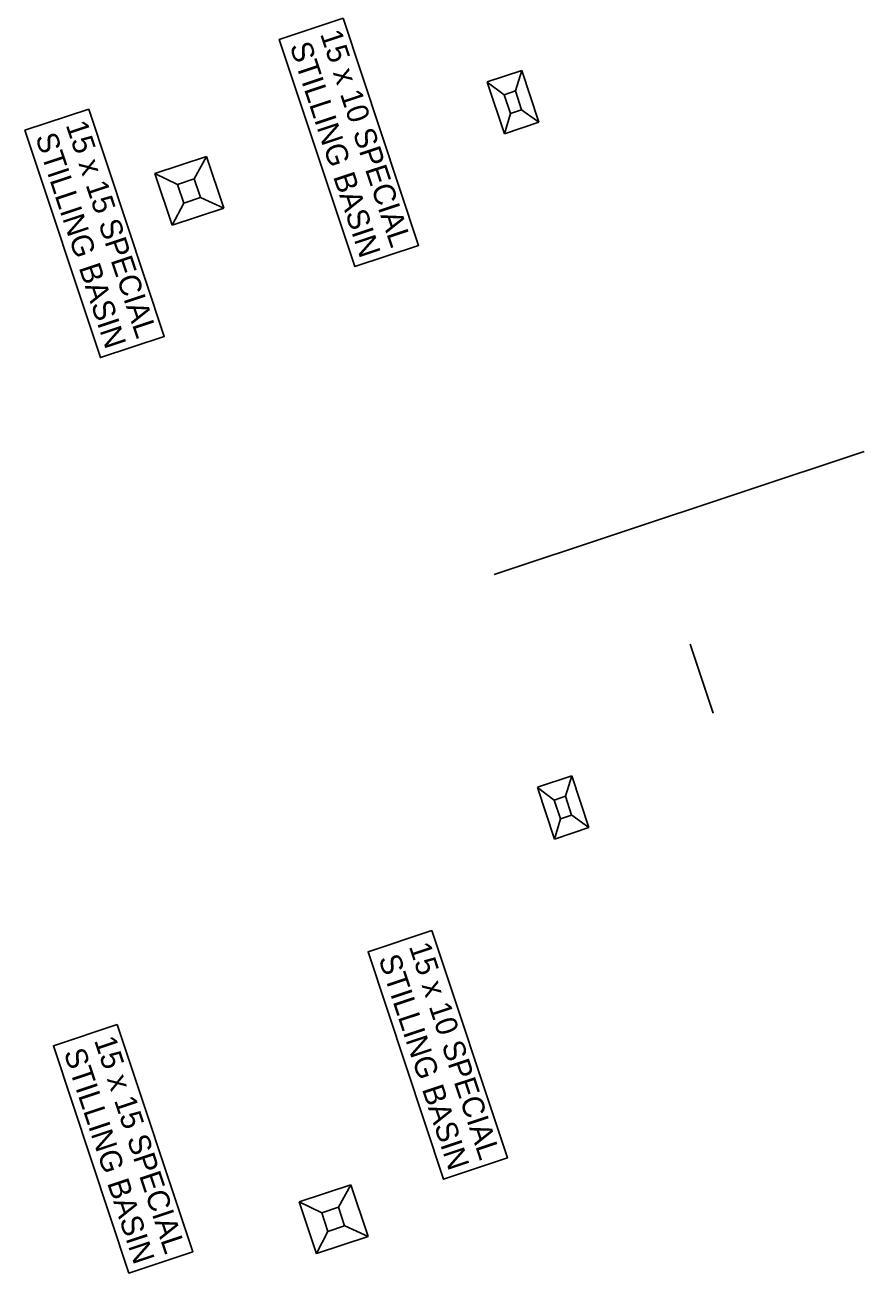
# Model space of a CAD drawing. Extents: x 400935 to 481562, y 415700 to 505362.
# Drawn here: x 401542.1 to 401773.5, y 419185.6 to 419529.4 of the extents above; entities that cross this region are included whole.
import ezdxf

# ---------------------------------------------------------------- set-up
doc = ezdxf.new("R2010")
doc.units = 0
for name, color, linetype in [('Slope Drain Final', 7, 'Continuous'), ('Slope Drain Inlet Final CELL', 7, 'Continuous'), ('Special Stilling Basin 15 x 10 Both CELL', 7, 'Continuous'), ('Special Stilling Basin 15 x 10 Final CELL', 7, 'Continuous'), ('Special Stilling Basin 15 x 10 Note Both CELL', 7, 'Continuous'), ('Special Stilling Basin 15 x 10 Note Final CELL', 7, 'Continuous'), ('Special Stilling Basin 15 x 15 Both CELL', 7, 'Continuous'), ('Special Stilling Basin 15 x 15 Final CELL', 7, 'Continuous'), ('Special Stilling Basin 15 x 15 Note Both CELL', 7, 'Continuous'), ('Special Stilling Basin 15 x 15 Note Final CELL', 7, 'Continuous')]:
    doc.layers.add(name, color=color, linetype=linetype)

msp = doc.modelspace()

# ---------------------------------------------------------------- linework, layer by layer
at = {"layer": 'Slope Drain Final'}
msp.add_line((401773.48, 419411.91), (401671.5, 419378.01), dxfattribs=at)
msp.add_line((401773.48, 419411.91), (401671.5, 419378.01), dxfattribs=at)
msp.add_line((401773.48, 419411.91), (401671.5, 419378.01), dxfattribs=at)
msp.add_line((401773.48, 419411.91), (401671.5, 419378.01), dxfattribs=at)
msp.add_line((401773.48, 419411.91), (401671.5, 419378.01), dxfattribs=at)
msp.add_line((401773.48, 419411.91), (401671.5, 419378.01), dxfattribs=at)
at = {"layer": 'Slope Drain Inlet Final CELL'}
msp.add_line((401725.56, 419358.83), (401731.87, 419339.85), dxfattribs=at)
msp.add_line((401725.56, 419358.83), (401731.87, 419339.85), dxfattribs=at)
msp.add_line((401725.56, 419358.83), (401731.87, 419339.85), dxfattribs=at)
msp.add_line((401725.56, 419358.83), (401731.87, 419339.85), dxfattribs=at)
msp.add_line((401725.56, 419358.83), (401731.87, 419339.85), dxfattribs=at)
msp.add_line((401725.56, 419358.83), (401731.87, 419339.85), dxfattribs=at)
at = {"layer": 'Special Stilling Basin 15 x 10 Both CELL'}
for p, q in [((401669.62, 419513.72), (401679.11, 419516.86)), ((401669.62, 419513.72), (401679.11, 419516.86)), ((401669.62, 419513.72), (401679.11, 419516.86)), ((401669.62, 419513.72), (401679.11, 419516.86)), ((401669.62, 419513.72), (401679.11, 419516.86)), ((401669.62, 419513.72), (401679.11, 419516.86)), ((401677.36, 419511.24), (401679.11, 419516.86)), ((401677.36, 419511.24), (401679.11, 419516.86)), ((401677.36, 419511.24), (401679.11, 419516.86)), ((401677.36, 419511.24), (401679.11, 419516.86)), ((401677.36, 419511.24), (401679.11, 419516.86)), ((401677.36, 419511.24), (401679.11, 419516.86)), ((401679.11, 419516.86), (401683.84, 419502.63)), ((401679.11, 419516.86), (401683.84, 419502.63)), ((401679.11, 419516.86), (401683.84, 419502.63)), ((401679.11, 419516.86), (401683.84, 419502.63)), ((401679.11, 419516.86), (401683.84, 419502.63)), ((401679.11, 419516.86), (401683.84, 419502.63)), ((401669.62, 419513.69), (401674.28, 419510.17)), ((401674.35, 419499.45), (401669.62, 419513.69)), ((401669.62, 419513.69), (401674.28, 419510.17)), ((401674.35, 419499.45), (401669.62, 419513.69)), ((401669.62, 419513.69), (401674.28, 419510.17)), ((401674.35, 419499.45), (401669.62, 419513.69)), ((401669.62, 419513.69), (401674.28, 419510.17)), ((401674.35, 419499.45), (401669.62, 419513.69)), ((401669.62, 419513.69), (401674.28, 419510.17)), ((401674.35, 419499.45), (401669.62, 419513.69)), ((401669.62, 419513.69), (401674.28, 419510.17)), ((401674.35, 419499.45), (401669.62, 419513.69)), ((401674.28, 419510.2), (401677.36, 419511.24)), ((401674.28, 419510.2), (401677.36, 419511.24)), ((401674.28, 419510.2), (401677.36, 419511.24)), ((401674.28, 419510.2), (401677.36, 419511.24)), ((401674.28, 419510.2), (401677.36, 419511.24)), ((401674.28, 419510.2), (401677.36, 419511.24)), ((401675.98, 419505.05), (401674.28, 419510.17)), ((401675.98, 419505.05), (401674.28, 419510.17)), ((401675.98, 419505.05), (401674.28, 419510.17)), ((401675.98, 419505.05), (401674.28, 419510.17)), ((401675.98, 419505.05), (401674.28, 419510.17)), ((401675.98, 419505.05), (401674.28, 419510.17)), ((401677.36, 419511.24), (401679.05, 419506.07)), ((401677.36, 419511.24), (401679.05, 419506.07)), ((401677.36, 419511.24), (401679.05, 419506.07)), ((401677.36, 419511.24), (401679.05, 419506.07)), ((401677.36, 419511.24), (401679.05, 419506.07)), ((401677.36, 419511.24), (401679.05, 419506.07)), ((401675.98, 419505.05), (401674.35, 419499.47)), ((401675.98, 419505.05), (401674.35, 419499.47)), ((401675.98, 419505.05), (401674.35, 419499.47)), ((401675.98, 419505.05), (401674.35, 419499.47)), ((401675.98, 419505.05), (401674.35, 419499.47)), ((401675.98, 419505.05), (401674.35, 419499.47)), ((401679.05, 419506.07), (401675.98, 419505.05)), ((401679.05, 419506.07), (401675.98, 419505.05)), ((401679.05, 419506.07), (401675.98, 419505.05)), ((401679.05, 419506.07), (401675.98, 419505.05)), ((401679.05, 419506.07), (401675.98, 419505.05)), ((401679.05, 419506.07), (401675.98, 419505.05)), ((401679.08, 419506.07), (401683.84, 419502.63)), ((401679.08, 419506.07), (401683.84, 419502.63)), ((401679.08, 419506.07), (401683.84, 419502.63)), ((401679.08, 419506.07), (401683.84, 419502.63)), ((401679.08, 419506.07), (401683.84, 419502.63)), ((401679.08, 419506.07), (401683.84, 419502.63)), ((401683.84, 419502.63), (401674.35, 419499.47)), ((401683.84, 419502.63), (401674.35, 419499.47)), ((401683.84, 419502.63), (401674.35, 419499.47)), ((401683.84, 419502.63), (401674.35, 419499.47)), ((401683.84, 419502.63), (401674.35, 419499.47)), ((401683.84, 419502.63), (401674.35, 419499.47))]:
    msp.add_line(p, q, dxfattribs=at)
at = {"layer": 'Special Stilling Basin 15 x 10 Final CELL'}
for p, q in [((401683.42, 419319.39), (401692.91, 419322.54)), ((401683.42, 419319.39), (401692.91, 419322.54)), ((401683.42, 419319.39), (401692.91, 419322.54)), ((401683.42, 419319.39), (401692.91, 419322.54)), ((401683.42, 419319.39), (401692.91, 419322.54)), ((401683.42, 419319.39), (401692.91, 419322.54)), ((401683.42, 419319.37), (401688.08, 419315.84)), ((401688.15, 419305.12), (401683.42, 419319.37)), ((401683.42, 419319.37), (401688.08, 419315.84)), ((401688.15, 419305.12), (401683.42, 419319.37)), ((401683.42, 419319.37), (401688.08, 419315.84)), ((401688.15, 419305.12), (401683.42, 419319.37)), ((401683.42, 419319.37), (401688.08, 419315.84)), ((401688.15, 419305.12), (401683.42, 419319.37)), ((401683.42, 419319.37), (401688.08, 419315.84)), ((401688.15, 419305.12), (401683.42, 419319.37)), ((401683.42, 419319.37), (401688.08, 419315.84)), ((401688.15, 419305.12), (401683.42, 419319.37)), ((401691.16, 419316.91), (401692.91, 419322.54)), ((401691.16, 419316.91), (401692.91, 419322.54)), ((401691.16, 419316.91), (401692.91, 419322.54)), ((401691.16, 419316.91), (401692.91, 419322.54)), ((401691.16, 419316.91), (401692.91, 419322.54)), ((401691.16, 419316.91), (401692.91, 419322.54)), ((401692.91, 419322.54), (401697.64, 419308.3)), ((401692.91, 419322.54), (401697.64, 419308.3)), ((401692.91, 419322.54), (401697.64, 419308.3)), ((401692.91, 419322.54), (401697.64, 419308.3)), ((401692.91, 419322.54), (401697.64, 419308.3)), ((401692.91, 419322.54), (401697.64, 419308.3)), ((401688.08, 419315.88), (401691.16, 419316.91)), ((401688.08, 419315.88), (401691.16, 419316.91)), ((401688.08, 419315.88), (401691.16, 419316.91)), ((401688.08, 419315.88), (401691.16, 419316.91)), ((401688.08, 419315.88), (401691.16, 419316.91)), ((401688.08, 419315.88), (401691.16, 419316.91)), ((401689.78, 419310.73), (401688.08, 419315.84)), ((401689.78, 419310.73), (401688.08, 419315.84)), ((401689.78, 419310.73), (401688.08, 419315.84)), ((401689.78, 419310.73), (401688.08, 419315.84)), ((401689.78, 419310.73), (401688.08, 419315.84)), ((401689.78, 419310.73), (401688.08, 419315.84)), ((401691.16, 419316.91), (401692.85, 419311.75)), ((401691.16, 419316.91), (401692.85, 419311.75)), ((401691.16, 419316.91), (401692.85, 419311.75)), ((401691.16, 419316.91), (401692.85, 419311.75)), ((401691.16, 419316.91), (401692.85, 419311.75)), ((401691.16, 419316.91), (401692.85, 419311.75)), ((401689.78, 419310.73), (401688.15, 419305.14)), ((401689.78, 419310.73), (401688.15, 419305.14)), ((401689.78, 419310.73), (401688.15, 419305.14)), ((401689.78, 419310.73), (401688.15, 419305.14)), ((401689.78, 419310.73), (401688.15, 419305.14)), ((401689.78, 419310.73), (401688.15, 419305.14)), ((401692.85, 419311.75), (401689.78, 419310.73)), ((401692.85, 419311.75), (401689.78, 419310.73)), ((401692.85, 419311.75), (401689.78, 419310.73)), ((401692.85, 419311.75), (401689.78, 419310.73)), ((401692.85, 419311.75), (401689.78, 419310.73)), ((401692.85, 419311.75), (401689.78, 419310.73)), ((401692.88, 419311.75), (401697.64, 419308.3)), ((401692.88, 419311.75), (401697.64, 419308.3)), ((401692.88, 419311.75), (401697.64, 419308.3)), ((401692.88, 419311.75), (401697.64, 419308.3)), ((401692.88, 419311.75), (401697.64, 419308.3)), ((401692.88, 419311.75), (401697.64, 419308.3)), ((401697.64, 419308.3), (401688.15, 419305.14)), ((401697.64, 419308.3), (401688.15, 419305.14)), ((401697.64, 419308.3), (401688.15, 419305.14)), ((401697.64, 419308.3), (401688.15, 419305.14)), ((401697.64, 419308.3), (401688.15, 419305.14)), ((401697.64, 419308.3), (401688.15, 419305.14))]:
    msp.add_line(p, q, dxfattribs=at)
at = {"layer": 'Special Stilling Basin 15 x 10 Note Both CELL'}
msp.add_lwpolyline([(401629.87, 419531.32), (401650.69, 419468.69), (401633.1, 419462.84), (401612.28, 419525.47)], close=True, dxfattribs=at)
msp.add_lwpolyline([(401629.87, 419531.32), (401650.69, 419468.69), (401633.1, 419462.84), (401612.28, 419525.47)], close=True, dxfattribs=at)
msp.add_lwpolyline([(401629.87, 419531.32), (401650.69, 419468.69), (401633.1, 419462.84), (401612.28, 419525.47)], close=True, dxfattribs=at)
msp.add_lwpolyline([(401629.87, 419531.32), (401650.69, 419468.69), (401633.1, 419462.84), (401612.28, 419525.47)], close=True, dxfattribs=at)
msp.add_lwpolyline([(401629.87, 419531.32), (401650.69, 419468.69), (401633.1, 419462.84), (401612.28, 419525.47)], close=True, dxfattribs=at)
msp.add_lwpolyline([(401629.87, 419531.32), (401650.69, 419468.69), (401633.1, 419462.84), (401612.28, 419525.47)], close=True, dxfattribs=at)
at = {"layer": 'Special Stilling Basin 15 x 10 Note Final CELL'}
msp.add_lwpolyline([(401654.35, 419279.91), (401675.17, 419217.28), (401657.58, 419211.43), (401636.76, 419274.06)], close=True, dxfattribs=at)
msp.add_lwpolyline([(401654.35, 419279.91), (401675.17, 419217.28), (401657.58, 419211.43), (401636.76, 419274.06)], close=True, dxfattribs=at)
msp.add_lwpolyline([(401654.35, 419279.91), (401675.17, 419217.28), (401657.58, 419211.43), (401636.76, 419274.06)], close=True, dxfattribs=at)
msp.add_lwpolyline([(401654.35, 419279.91), (401675.17, 419217.28), (401657.58, 419211.43), (401636.76, 419274.06)], close=True, dxfattribs=at)
msp.add_lwpolyline([(401654.35, 419279.91), (401675.17, 419217.28), (401657.58, 419211.43), (401636.76, 419274.06)], close=True, dxfattribs=at)
msp.add_lwpolyline([(401654.35, 419279.91), (401675.17, 419217.28), (401657.58, 419211.43), (401636.76, 419274.06)], close=True, dxfattribs=at)
at = {"layer": 'Special Stilling Basin 15 x 15 Both CELL'}
for p, q in [((401577.97, 419488.5), (401592.22, 419493.22)), ((401577.97, 419488.5), (401592.22, 419493.22)), ((401577.97, 419488.5), (401592.22, 419493.22)), ((401577.97, 419488.5), (401592.22, 419493.22)), ((401577.97, 419488.5), (401592.22, 419493.22)), ((401577.97, 419488.5), (401592.22, 419493.22)), ((401588.83, 419487.05), (401592.22, 419493.22)), ((401588.83, 419487.05), (401592.22, 419493.22)), ((401588.83, 419487.05), (401592.22, 419493.22)), ((401588.83, 419487.05), (401592.22, 419493.22)), ((401588.83, 419487.05), (401592.22, 419493.22)), ((401588.83, 419487.05), (401592.22, 419493.22)), ((401592.22, 419493.22), (401596.94, 419478.99)), ((401592.22, 419493.22), (401596.94, 419478.99)), ((401592.22, 419493.22), (401596.94, 419478.99)), ((401592.22, 419493.22), (401596.94, 419478.99)), ((401592.22, 419493.22), (401596.94, 419478.99)), ((401592.22, 419493.22), (401596.94, 419478.99)), ((401577.98, 419488.47), (401584.21, 419485.47)), ((401582.71, 419474.23), (401577.98, 419488.47)), ((401577.98, 419488.47), (401584.21, 419485.47)), ((401582.71, 419474.23), (401577.98, 419488.47)), ((401577.98, 419488.47), (401584.21, 419485.47)), ((401582.71, 419474.23), (401577.98, 419488.47)), ((401577.98, 419488.47), (401584.21, 419485.47)), ((401582.71, 419474.23), (401577.98, 419488.47)), ((401577.98, 419488.47), (401584.21, 419485.47)), ((401582.71, 419474.23), (401577.98, 419488.47)), ((401577.98, 419488.47), (401584.21, 419485.47)), ((401582.71, 419474.23), (401577.98, 419488.47)), ((401585.91, 419480.36), (401584.21, 419485.47)), ((401585.91, 419480.36), (401584.21, 419485.47)), ((401585.91, 419480.36), (401584.21, 419485.47)), ((401585.91, 419480.36), (401584.21, 419485.47)), ((401585.91, 419480.36), (401584.21, 419485.47)), ((401585.91, 419480.36), (401584.21, 419485.47)), ((401584.22, 419485.51), (401588.83, 419487.05)), ((401584.22, 419485.51), (401588.83, 419487.05)), ((401584.22, 419485.51), (401588.83, 419487.05)), ((401584.22, 419485.51), (401588.83, 419487.05)), ((401584.22, 419485.51), (401588.83, 419487.05)), ((401584.22, 419485.51), (401588.83, 419487.05)), ((401588.83, 419487.05), (401590.51, 419481.88)), ((401588.83, 419487.05), (401590.51, 419481.88)), ((401588.83, 419487.05), (401590.51, 419481.88)), ((401588.83, 419487.05), (401590.51, 419481.88)), ((401588.83, 419487.05), (401590.51, 419481.88)), ((401588.83, 419487.05), (401590.51, 419481.88)), ((401590.51, 419481.88), (401585.91, 419480.36)), ((401590.51, 419481.88), (401585.91, 419480.36)), ((401590.51, 419481.88), (401585.91, 419480.36)), ((401590.51, 419481.88), (401585.91, 419480.36)), ((401590.51, 419481.88), (401585.91, 419480.36)), ((401590.51, 419481.88), (401585.91, 419480.36)), ((401590.55, 419481.89), (401596.94, 419478.99)), ((401590.55, 419481.89), (401596.94, 419478.99)), ((401590.55, 419481.89), (401596.94, 419478.99)), ((401590.55, 419481.89), (401596.94, 419478.99)), ((401590.55, 419481.89), (401596.94, 419478.99)), ((401590.55, 419481.89), (401596.94, 419478.99)), ((401585.91, 419480.36), (401582.71, 419474.25)), ((401585.91, 419480.36), (401582.71, 419474.25)), ((401585.91, 419480.36), (401582.71, 419474.25)), ((401585.91, 419480.36), (401582.71, 419474.25)), ((401585.91, 419480.36), (401582.71, 419474.25)), ((401585.91, 419480.36), (401582.71, 419474.25)), ((401596.94, 419478.99), (401582.71, 419474.25)), ((401596.94, 419478.99), (401582.71, 419474.25)), ((401596.94, 419478.99), (401582.71, 419474.25)), ((401596.94, 419478.99), (401582.71, 419474.25)), ((401596.94, 419478.99), (401582.71, 419474.25)), ((401596.94, 419478.99), (401582.71, 419474.25))]:
    msp.add_line(p, q, dxfattribs=at)
at = {"layer": 'Special Stilling Basin 15 x 15 Final CELL'}
for p, q in [((401617.76, 419205.17), (401632, 419209.9)), ((401617.76, 419205.17), (401632, 419209.9)), ((401617.76, 419205.17), (401632, 419209.9)), ((401617.76, 419205.17), (401632, 419209.9)), ((401617.76, 419205.17), (401632, 419209.9)), ((401617.76, 419205.17), (401632, 419209.9)), ((401628.62, 419203.73), (401632, 419209.9)), ((401628.62, 419203.73), (401632, 419209.9)), ((401628.62, 419203.73), (401632, 419209.9)), ((401628.62, 419203.73), (401632, 419209.9)), ((401628.62, 419203.73), (401632, 419209.9)), ((401628.62, 419203.73), (401632, 419209.9)), ((401632, 419209.9), (401636.73, 419195.66)), ((401632, 419209.9), (401636.73, 419195.66)), ((401632, 419209.9), (401636.73, 419195.66)), ((401632, 419209.9), (401636.73, 419195.66)), ((401632, 419209.9), (401636.73, 419195.66)), ((401632, 419209.9), (401636.73, 419195.66)), ((401617.77, 419205.15), (401623.99, 419202.15)), ((401622.49, 419190.9), (401617.77, 419205.15)), ((401617.77, 419205.15), (401623.99, 419202.15)), ((401622.49, 419190.9), (401617.77, 419205.15)), ((401617.77, 419205.15), (401623.99, 419202.15)), ((401622.49, 419190.9), (401617.77, 419205.15)), ((401617.77, 419205.15), (401623.99, 419202.15)), ((401622.49, 419190.9), (401617.77, 419205.15)), ((401617.77, 419205.15), (401623.99, 419202.15)), ((401622.49, 419190.9), (401617.77, 419205.15)), ((401617.77, 419205.15), (401623.99, 419202.15)), ((401622.49, 419190.9), (401617.77, 419205.15)), ((401624, 419202.19), (401628.62, 419203.73)), ((401624, 419202.19), (401628.62, 419203.73)), ((401624, 419202.19), (401628.62, 419203.73)), ((401624, 419202.19), (401628.62, 419203.73)), ((401624, 419202.19), (401628.62, 419203.73)), ((401624, 419202.19), (401628.62, 419203.73)), ((401628.62, 419203.73), (401630.29, 419198.56)), ((401628.62, 419203.73), (401630.29, 419198.56)), ((401628.62, 419203.73), (401630.29, 419198.56)), ((401628.62, 419203.73), (401630.29, 419198.56)), ((401628.62, 419203.73), (401630.29, 419198.56)), ((401628.62, 419203.73), (401630.29, 419198.56)), ((401625.69, 419197.03), (401623.99, 419202.15)), ((401625.69, 419197.03), (401623.99, 419202.15)), ((401625.69, 419197.03), (401623.99, 419202.15)), ((401625.69, 419197.03), (401623.99, 419202.15)), ((401625.69, 419197.03), (401623.99, 419202.15)), ((401625.69, 419197.03), (401623.99, 419202.15)), ((401625.69, 419197.03), (401622.49, 419190.92)), ((401625.69, 419197.03), (401622.49, 419190.92)), ((401625.69, 419197.03), (401622.49, 419190.92)), ((401625.69, 419197.03), (401622.49, 419190.92)), ((401625.69, 419197.03), (401622.49, 419190.92)), ((401625.69, 419197.03), (401622.49, 419190.92)), ((401636.73, 419195.66), (401622.49, 419190.92)), ((401636.73, 419195.66), (401622.49, 419190.92)), ((401636.73, 419195.66), (401622.49, 419190.92)), ((401636.73, 419195.66), (401622.49, 419190.92)), ((401636.73, 419195.66), (401622.49, 419190.92)), ((401636.73, 419195.66), (401622.49, 419190.92)), ((401630.29, 419198.56), (401625.69, 419197.03)), ((401630.29, 419198.56), (401625.69, 419197.03)), ((401630.29, 419198.56), (401625.69, 419197.03)), ((401630.29, 419198.56), (401625.69, 419197.03)), ((401630.29, 419198.56), (401625.69, 419197.03)), ((401630.29, 419198.56), (401625.69, 419197.03)), ((401630.33, 419198.56), (401636.73, 419195.66)), ((401630.33, 419198.56), (401636.73, 419195.66)), ((401630.33, 419198.56), (401636.73, 419195.66)), ((401630.33, 419198.56), (401636.73, 419195.66)), ((401630.33, 419198.56), (401636.73, 419195.66)), ((401630.33, 419198.56), (401636.73, 419195.66))]:
    msp.add_line(p, q, dxfattribs=at)
at = {"layer": 'Special Stilling Basin 15 x 15 Note Both CELL'}
msp.add_lwpolyline([(401559.74, 419506.26), (401580.56, 419443.63), (401562.97, 419437.79), (401542.15, 419500.42)], close=True, dxfattribs=at)
msp.add_lwpolyline([(401559.74, 419506.26), (401580.56, 419443.63), (401562.97, 419437.79), (401542.15, 419500.42)], close=True, dxfattribs=at)
msp.add_lwpolyline([(401559.74, 419506.26), (401580.56, 419443.63), (401562.97, 419437.79), (401542.15, 419500.42)], close=True, dxfattribs=at)
msp.add_lwpolyline([(401559.74, 419506.26), (401580.56, 419443.63), (401562.97, 419437.79), (401542.15, 419500.42)], close=True, dxfattribs=at)
msp.add_lwpolyline([(401559.74, 419506.26), (401580.56, 419443.63), (401562.97, 419437.79), (401542.15, 419500.42)], close=True, dxfattribs=at)
msp.add_lwpolyline([(401559.74, 419506.26), (401580.56, 419443.63), (401562.97, 419437.79), (401542.15, 419500.42)], close=True, dxfattribs=at)
at = {"layer": 'Special Stilling Basin 15 x 15 Note Final CELL'}
msp.add_lwpolyline([(401567.58, 419254.05), (401588.39, 419191.42), (401570.8, 419185.57), (401549.99, 419248.2)], close=True, dxfattribs=at)
msp.add_lwpolyline([(401567.58, 419254.05), (401588.39, 419191.42), (401570.8, 419185.57), (401549.99, 419248.2)], close=True, dxfattribs=at)
msp.add_lwpolyline([(401567.58, 419254.05), (401588.39, 419191.42), (401570.8, 419185.57), (401549.99, 419248.2)], close=True, dxfattribs=at)
msp.add_lwpolyline([(401567.58, 419254.05), (401588.39, 419191.42), (401570.8, 419185.57), (401549.99, 419248.2)], close=True, dxfattribs=at)
msp.add_lwpolyline([(401567.58, 419254.05), (401588.39, 419191.42), (401570.8, 419185.57), (401549.99, 419248.2)], close=True, dxfattribs=at)
msp.add_lwpolyline([(401567.58, 419254.05), (401588.39, 419191.42), (401570.8, 419185.57), (401549.99, 419248.2)], close=True, dxfattribs=at)

# ---------------------------------------------------------------- texts
at = {"layer": 'Special Stilling Basin 15 x 10 Note Both CELL'}
for s, p in [('15 x 10 SPECIAL', (401623.47, 419526.97)), ('15 x 10 SPECIAL', (401623.47, 419526.97)), ('15 x 10 SPECIAL', (401623.47, 419526.97)), ('15 x 10 SPECIAL', (401623.47, 419526.97)), ('15 x 10 SPECIAL', (401623.47, 419526.97)), ('15 x 10 SPECIAL', (401623.47, 419526.97)), ('STILLING BASIN', (401615.09, 419523.65)), ('STILLING BASIN', (401615.09, 419523.65)), ('STILLING BASIN', (401615.09, 419523.65)), ('STILLING BASIN', (401615.09, 419523.65)), ('STILLING BASIN', (401615.09, 419523.65)), ('STILLING BASIN', (401615.09, 419523.65))]:
    msp.add_text(s, height=6, rotation=288.3867, dxfattribs=at).set_placement(p)
at = {"layer": 'Special Stilling Basin 15 x 10 Note Final CELL'}
for s, p in [('15 x 10 SPECIAL', (401647.95, 419275.56)), ('15 x 10 SPECIAL', (401647.95, 419275.56)), ('15 x 10 SPECIAL', (401647.95, 419275.56)), ('15 x 10 SPECIAL', (401647.95, 419275.56)), ('15 x 10 SPECIAL', (401647.95, 419275.56)), ('15 x 10 SPECIAL', (401647.95, 419275.56)), ('STILLING BASIN', (401639.57, 419272.24)), ('STILLING BASIN', (401639.57, 419272.24)), ('STILLING BASIN', (401639.57, 419272.24)), ('STILLING BASIN', (401639.57, 419272.24)), ('STILLING BASIN', (401639.57, 419272.24)), ('STILLING BASIN', (401639.57, 419272.24))]:
    msp.add_text(s, height=6, rotation=288.3867, dxfattribs=at).set_placement(p)
at = {"layer": 'Special Stilling Basin 15 x 15 Note Both CELL'}
for s, p in [('15 x 15 SPECIAL', (401553.34, 419501.92)), ('15 x 15 SPECIAL', (401553.34, 419501.92)), ('15 x 15 SPECIAL', (401553.34, 419501.92)), ('15 x 15 SPECIAL', (401553.34, 419501.92)), ('15 x 15 SPECIAL', (401553.34, 419501.92)), ('15 x 15 SPECIAL', (401553.34, 419501.92)), ('STILLING BASIN', (401544.96, 419498.59)), ('STILLING BASIN', (401544.96, 419498.59)), ('STILLING BASIN', (401544.96, 419498.59)), ('STILLING BASIN', (401544.96, 419498.59)), ('STILLING BASIN', (401544.96, 419498.59)), ('STILLING BASIN', (401544.96, 419498.59))]:
    msp.add_text(s, height=6, rotation=288.3867, dxfattribs=at).set_placement(p)
at = {"layer": 'Special Stilling Basin 15 x 15 Note Final CELL'}
for s, p in [('15 x 15 SPECIAL', (401561.18, 419249.7)), ('15 x 15 SPECIAL', (401561.18, 419249.7)), ('15 x 15 SPECIAL', (401561.18, 419249.7)), ('15 x 15 SPECIAL', (401561.18, 419249.7)), ('15 x 15 SPECIAL', (401561.18, 419249.7)), ('15 x 15 SPECIAL', (401561.18, 419249.7)), ('STILLING BASIN', (401552.8, 419246.37)), ('STILLING BASIN', (401552.8, 419246.37)), ('STILLING BASIN', (401552.8, 419246.37)), ('STILLING BASIN', (401552.8, 419246.37)), ('STILLING BASIN', (401552.8, 419246.37)), ('STILLING BASIN', (401552.8, 419246.37))]:
    msp.add_text(s, height=6, rotation=288.3867, dxfattribs=at).set_placement(p)

doc.saveas('drawing.dxf')
